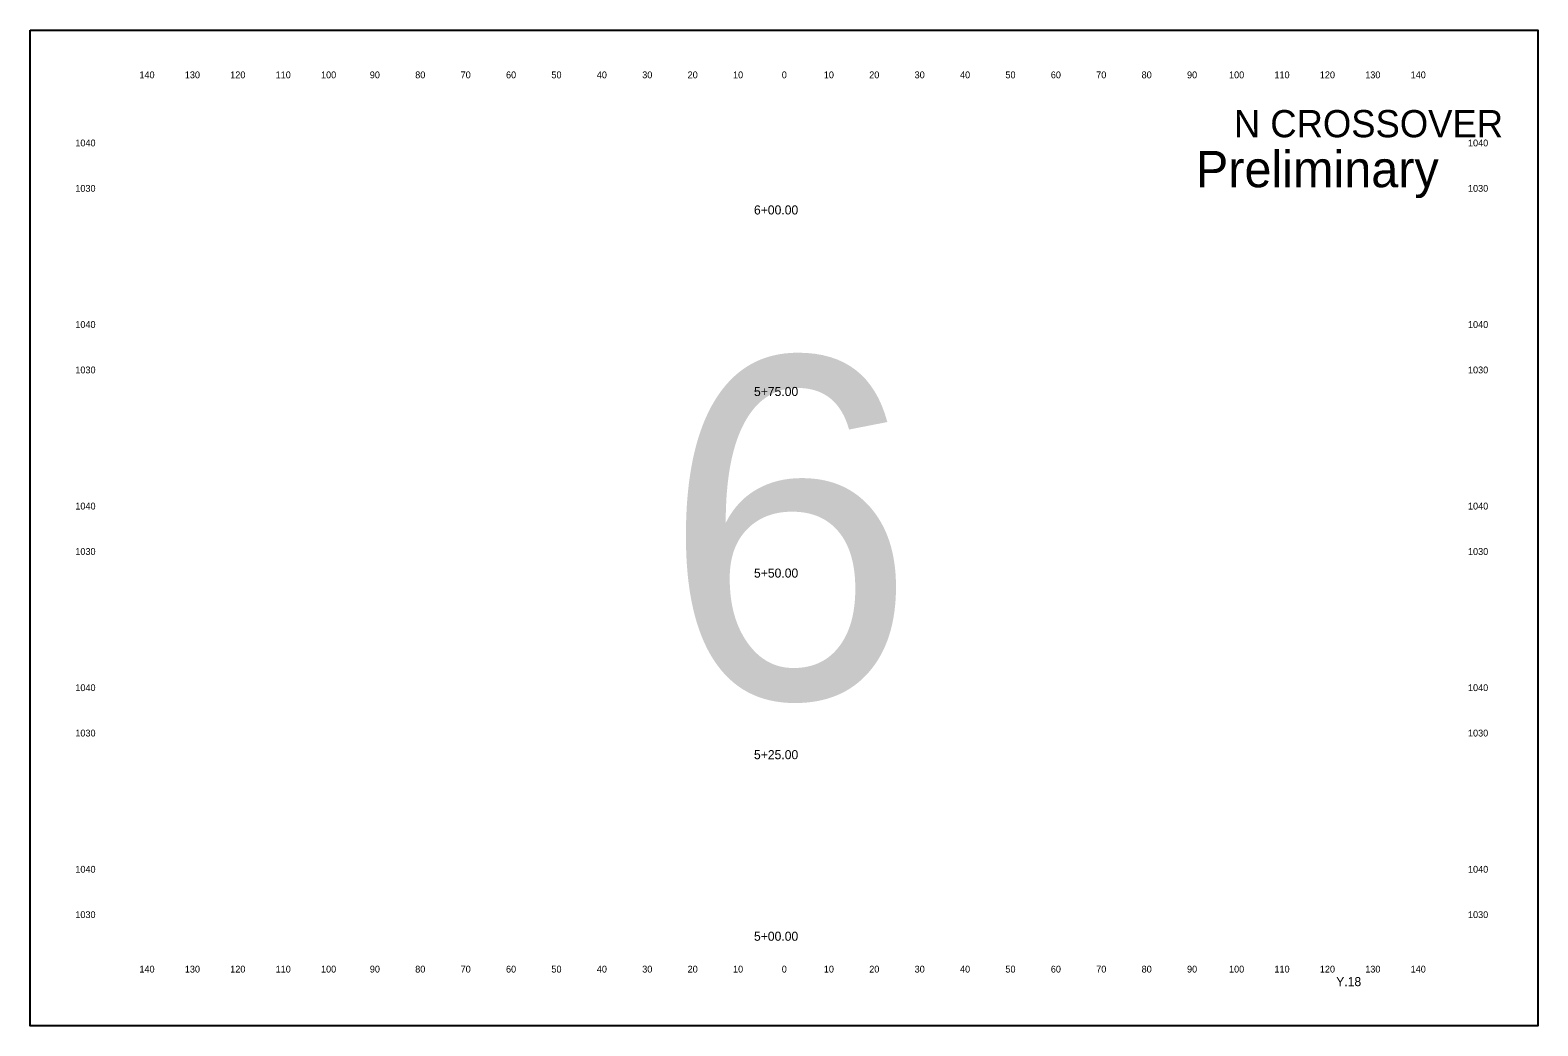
# Model space of a CAD drawing. Extents: x 10123 to 14767, y 9730 to 9950.
# Drawn here: x 11923.2 to 12255.3, y 9730.3 to 9949.6 of the extents above; entities that cross this region are included whole.
import ezdxf

# ---------------------------------------------------------------- set-up
doc = ezdxf.new("R2010")
doc.units = 0
for name, color, linetype in [('dsnTextCpn', 7, 'Continuous'), ('dsnTextCpnTitleSheetLocDesc', 7, 'Continuous'), ('dsnTextCpnTitleSheetPIN', 7, 'Continuous'), ('dsnTextCpnTitleSheetWorkType', 7, 'Continuous')]:
    doc.layers.add(name, color=color, linetype=linetype)

msp = doc.modelspace()

# ---------------------------------------------------------------- linework, layer by layer
at = {"layer": 'dsnTextCpnTitleSheetWorkType'}
msp.add_lwpolyline([(11923.21, 9949.6), (12255.29, 9949.6), (12255.29, 9730.26), (11923.21, 9730.26)], close=True, dxfattribs=at)

# ---------------------------------------------------------------- texts
at = {"layer": 'dsnTextCpn'}
for s, height, p in [('140', 1.5, (11947.27, 9939)), ('130', 1.5, (11957.27, 9939)), ('120', 1.5, (11967.27, 9939)), ('110', 1.5, (11977.27, 9939)), ('100', 1.5, (11987.27, 9939)), ('90', 1.5, (11998.02, 9939)), ('80', 1.5, (12008.02, 9939)), ('70', 1.5, (12018.02, 9939)), ('60', 1.5, (12028.02, 9939)), ('50', 1.5, (12038.02, 9939)), ('40', 1.5, (12048.02, 9939)), ('30', 1.5, (12058.02, 9939)), ('20', 1.5, (12068.02, 9939)), ('10', 1.5, (12078.02, 9939)), ('0', 1.5, (12088.76, 9939)), ('0', 1.5, (12088.76, 9939)), ('10', 1.5, (12098.02, 9939)), ('20', 1.5, (12108.02, 9939)), ('30', 1.5, (12118.02, 9939)), ('40', 1.5, (12128.02, 9939)), ('50', 1.5, (12138.02, 9939)), ('60', 1.5, (12148.02, 9939)), ('70', 1.5, (12158.02, 9939)), ('80', 1.5, (12168.02, 9939)), ('90', 1.5, (12178.02, 9939)), ('100', 1.5, (12187.27, 9939)), ('110', 1.5, (12197.27, 9939)), ('120', 1.5, (12207.27, 9939)), ('130', 1.5, (12217.27, 9939)), ('140', 1.5, (12227.27, 9939)), ('N CROSSOVER', 6, (12188.34, 9926)), ('1040', 1.5, (11933.15, 9924)), ('1040', 1.5, (12239.9, 9924)), ('1030', 1.5, (11933.15, 9914)), ('1030', 1.5, (12239.9, 9914)), ('6+00.00', 2, (12082.64, 9909)), ('1040', 1.5, (11933.15, 9884)), ('1040', 1.5, (12239.9, 9884)), ('1030', 1.5, (11933.15, 9874)), ('1030', 1.5, (12239.9, 9874)), ('5+75.00', 2, (12082.64, 9869)), ('1040', 1.5, (11933.15, 9844)), ('1040', 1.5, (12239.9, 9844)), ('1030', 1.5, (11933.15, 9834)), ('1030', 1.5, (12239.9, 9834)), ('5+50.00', 2, (12082.64, 9829)), ('1040', 1.5, (11933.15, 9804)), ('1040', 1.5, (12239.9, 9804)), ('1030', 1.5, (11933.15, 9794)), ('1030', 1.5, (12239.9, 9794)), ('5+25.00', 2, (12082.64, 9789)), ('1040', 1.5, (11933.15, 9764)), ('1040', 1.5, (12239.9, 9764)), ('1030', 1.5, (11933.15, 9754)), ('1030', 1.5, (12239.9, 9754)), ('5+00.00', 2, (12082.64, 9749)), ('140', 1.5, (11947.27, 9742)), ('130', 1.5, (11957.27, 9742)), ('120', 1.5, (11967.27, 9742)), ('110', 1.5, (11977.27, 9742)), ('100', 1.5, (11987.27, 9742)), ('90', 1.5, (11998.02, 9742)), ('80', 1.5, (12008.02, 9742)), ('70', 1.5, (12018.02, 9742)), ('60', 1.5, (12028.02, 9742)), ('50', 1.5, (12038.02, 9742)), ('40', 1.5, (12048.02, 9742)), ('30', 1.5, (12058.02, 9742)), ('20', 1.5, (12068.02, 9742)), ('10', 1.5, (12078.02, 9742)), ('0', 1.5, (12088.76, 9742)), ('0', 1.5, (12088.76, 9742)), ('10', 1.5, (12098.02, 9742)), ('20', 1.5, (12108.02, 9742)), ('30', 1.5, (12118.02, 9742)), ('40', 1.5, (12128.02, 9742)), ('50', 1.5, (12138.02, 9742)), ('60', 1.5, (12148.02, 9742)), ('70', 1.5, (12158.02, 9742)), ('80', 1.5, (12168.02, 9742)), ('90', 1.5, (12178.02, 9742)), ('100', 1.5, (12187.27, 9742)), ('110', 1.5, (12197.27, 9742)), ('120', 1.5, (12207.27, 9742)), ('130', 1.5, (12217.27, 9742)), ('140', 1.5, (12227.27, 9742))]:
    msp.add_text(s, height=height, dxfattribs=at).set_placement(p)
at = {"layer": 'dsnTextCpnTitleSheetLocDesc'}
msp.add_text('Preliminary', height=8, dxfattribs=at).set_placement((12179.97, 9915))
at = {"layer": 'dsnTextCpnTitleSheetPIN'}
msp.add_text('Y.18', height=2, dxfattribs=at).set_placement((12210.88, 9739))
at = {"layer": 'dsnTextCpnTitleSheetWorkType'}
msp.add_text('6', height=75, dxfattribs=at).set_placement((12062.55, 9802.43))

doc.saveas('drawing.dxf')
